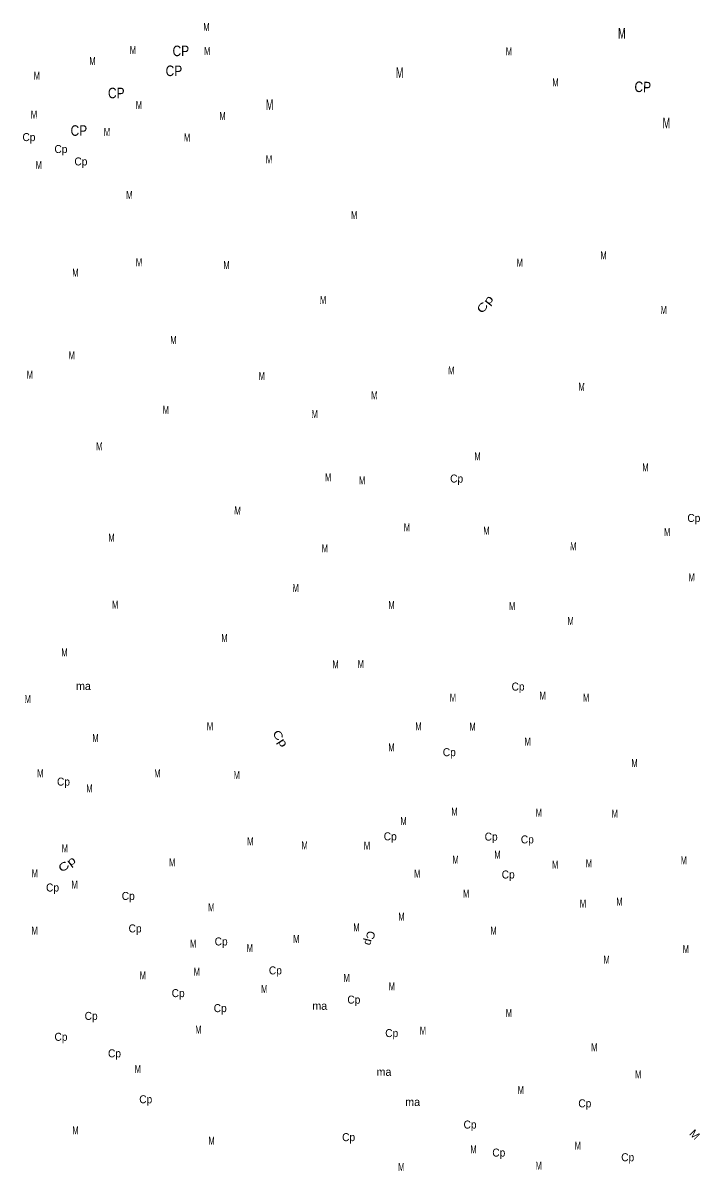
# Model space of a CAD drawing. Extents: x 713577 to 726626, y 7177731 to 7191794.
# Drawn here: x 716898 to 720111, y 7186341 to 7191792 of the extents above; entities that cross this region are included whole.
import ezdxf
from ezdxf.enums import TextEntityAlignment as Align

# ---------------------------------------------------------------- set-up
doc = ezdxf.new("R2010")
doc.units = 0
doc.header["$LTSCALE"] = 15
doc.layers.add('19', color=7, linetype='Continuous')

msp = doc.modelspace()

# ---------------------------------------------------------------- texts
at = {"layer": '19'}
for s, height, rotation, width, p in [('M', 38, 359.413, 0.65, (717768.22, 7191753.84)), ('M', 49.99, 359.812, 0.65, (719740.13, 7191717.98)), ('M', 38, 359.413, 0.65, (717419.25, 7191644.52)), ('M', 38, 359.413, 0.65, (717227.15, 7191592.51)), ('M', 38, 359.413, 0.65, (717772, 7191640.2)), ('M', 38, 359.413, 0.65, (719203.96, 7191637.88)), ('M', 49.99, 359.812, 0.65, (718685.63, 7191530.81)), ('M', 38, 359.549, 0.65, (716963.37, 7191522.42)), ('M', 38, 359.413, 0.65, (719424.92, 7191490.61)), ('CP', 50, 357.945, 0.85, (719838.79, 7191463.22)), ('M', 38, 359.549, 0.65, (717447.65, 7191383.21)), ('M', 50, 359.771, 0.65, (718068.11, 7191379.09)), ('M', 38, 359.549, 0.65, (716949.76, 7191338.04)), ('M', 38, 359.413, 0.65, (717844.69, 7191331.82)), ('M', 49.99, 359.812, 0.65, (719951.59, 7191291.84)), ('Cp', 38, 359.549, 0.95, (716925.89, 7191230.94)), ('M', 38, 359.549, 0.65, (717296.12, 7191255.64)), ('M', 38, 359.413, 0.65, (717676.41, 7191229.12)), ('Cp', 38, 359.549, 0.95, (717077.68, 7191174.32)), ('M', 38, 359.549, 0.65, (716972.43, 7191098.74)), ('Cp', 38, 359.549, 0.95, (717172.38, 7191115.43)), ('M', 38, 359.413, 0.65, (718065.11, 7191125.44)), ('M', 38, 359.549, 0.65, (717402.2, 7190955.89)), ('M', 38, 359.413, 0.65, (718469.52, 7190860.58)), ('M', 38, 359.413, 0.65, (719653.24, 7190670.15)), ('M', 38, 359.413, 0.65, (717448.08, 7190636.29)), ('M', 38, 359.413, 0.65, (717863.46, 7190623.36)), ('M', 38, 359.413, 0.65, (719255.56, 7190634.71)), ('M', 38, 359.549, 0.65, (717146.4, 7190587.65)), ('M', 38, 359.413, 0.65, (718321.81, 7190457.79)), ('Cp', 38, 52.123, 1.4, (719105.46, 7190445.02)), ('M', 38, 359.413, 0.65, (719938.74, 7190410.39)), ('M', 38, 359.413, 0.65, (717611.53, 7190268.07)), ('M', 38, 359.549, 0.65, (717129.03, 7190194.34)), ('M', 38, 359.413, 0.65, (718930.69, 7190122.96)), ('M', 38, 359.549, 0.65, (716929.98, 7190102.46)), ('M', 38, 359.413, 0.65, (718030.94, 7190097.39)), ('M', 38, 359.413, 0.65, (719549.05, 7190045.36)), ('M', 38, 359.413, 0.65, (718564.98, 7190005.35)), ('M', 38, 359.413, 0.65, (717575.74, 7189936.1)), ('M', 38, 359.413, 0.65, (718282.25, 7189916.16)), ('M', 38, 359.413, 0.65, (717259.62, 7189762.59)), ('M', 38, 359.413, 0.65, (719054.94, 7189715.97)), ('M', 38, 359.413, 0.65, (719852.06, 7189663)), ('M', 38, 359.413, 0.65, (718345.86, 7189616.34)), ('M', 38, 359.413, 0.65, (718507.28, 7189600.93)), ('Cp', 38, 359.413, 0.95, (718955.91, 7189609.88)), ('M', 38, 355.593, 0.75, (717914.45, 7189457.72)), ('Cp', 38, 359.413, 0.95, (720081.88, 7189422.65)), ('M', 38, 359.413, 0.65, (718719.78, 7189378.26)), ('M', 38, 359.413, 0.65, (719097.18, 7189362.39)), ('M', 38, 359.413, 0.65, (719955.1, 7189356.07)), ('M', 38, 359.549, 0.65, (717317.69, 7189329.29)), ('M', 38, 359.413, 0.65, (718330.33, 7189278.17)), ('M', 38, 359.413, 0.65, (719509.89, 7189287.96)), ('M', 38, 359.413, 0.65, (720071.44, 7189141.09)), ('M', 38, 359.413, 0.65, (718191.88, 7189090.85)), ('M', 38, 359.549, 0.65, (717335.16, 7189011.05)), ('M', 38, 359.99, 0.65, (718647.01, 7189009.54)), ('M', 38, 359.99, 0.65, (719219.66, 7189004.16)), ('M', 38, 359.99, 0.65, (719497.13, 7188933.39)), ('M', 38, 359.99, 0.65, (717853.98, 7188852.99)), ('M', 38, 359.549, 0.65, (717094.38, 7188784.3)), ('M', 38, 359.99, 0.65, (718381.42, 7188727.88)), ('M', 38, 359.99, 0.65, (718501.16, 7188729.84)), ('Cp', 38, 359.99, 0.95, (719247.65, 7188622.37)), ('M', 38, 359.549, 0.65, (716920, 7188563.09)), ('M', 38, 359.99, 0.65, (718938.54, 7188569.77)), ('M', 38, 359.99, 0.65, (719364.46, 7188578.8)), ('M', 38, 359.99, 0.65, (719570.63, 7188569.53)), ('M', 38, 359.99, 0.65, (717785.29, 7188433.41)), ('M', 38, 359.99, 0.65, (718774.96, 7188432.77)), ('M', 38, 359.99, 0.65, (719031.6, 7188432.07)), ('M', 38, 359.549, 0.65, (717241.71, 7188378.28)), ('Cp', 38, 303.457, 1.3, (718103.16, 7188384.49)), ('M', 38, 359.99, 0.65, (718646.63, 7188333.51)), ('M', 38, 359.99, 0.65, (719293.06, 7188361.16)), ('Cp', 38, 359.99, 0.95, (718921.34, 7188310.69)), ('M', 38, 359.99, 0.65, (716980.11, 7188211.09)), ('M', 38, 359.99, 0.65, (717535.54, 7188209.8)), ('M', 38, 359.99, 0.65, (719800.46, 7188258.68)), ('Cp', 38, 359.99, 0.95, (717089.88, 7188170.96)), ('M', 38, 359.99, 0.65, (717912.25, 7188202.15)), ('M', 38, 359.99, 0.65, (717212.98, 7188138.48)), ('M', 38, 359.99, 0.65, (718945.64, 7188028.38)), ('M', 38, 359.99, 0.65, (719346.11, 7188023.36)), ('M', 38, 359.99, 0.65, (719706.73, 7188019.2)), ('M', 38, 359.99, 0.65, (718704.23, 7187983.31)), ('M', 38, 359.99, 0.65, (717976.85, 7187886.78)), ('Cp', 38, 359.99, 0.95, (718640.88, 7187911.26)), ('Cp', 38, 359.99, 0.95, (719119.86, 7187909.85)), ('Cp', 38, 359.99, 0.95, (719291.72, 7187896.63)), ('M', 38, 359.99, 0.65, (717096.49, 7187854.15)), ('M', 38, 359.99, 0.65, (718234.47, 7187868.6)), ('M', 38, 359.99, 0.65, (718530.69, 7187866.56)), ('Cp', 38, 36.649, 1.35, (717117.47, 7187783.07)), ('M', 38, 359.99, 0.65, (717606.06, 7187787.23)), ('M', 38, 359.99, 0.65, (718951.21, 7187800.1)), ('M', 38, 359.99, 0.65, (719149.8, 7187824.15)), ('M', 38, 359.99, 0.65, (719423.91, 7187776.93)), ('M', 38, 359.99, 0.65, (719583.97, 7187782.7)), ('M', 38, 359.99, 0.65, (720033.96, 7187797.55)), ('M', 38, 359.99, 0.65, (716953.86, 7187736.25)), ('M', 38, 359.99, 0.65, (718769.1, 7187734.16)), ('Cp', 38, 359.99, 0.95, (719200.65, 7187730.06)), ('Cp', 38, 359.99, 0.95, (717038.03, 7187668.28)), ('M', 38, 359.99, 0.65, (717142.87, 7187681.46)), ('Cp', 38, 359.99, 0.95, (717397.22, 7187628.27)), ('M', 38, 359.99, 0.65, (719001.19, 7187639.7)), ('M', 38, 359.99, 0.65, (717791.41, 7187573.77)), ('M', 38, 359.99, 0.65, (719555.7, 7187592.1)), ('M', 38, 359.99, 0.65, (719728.76, 7187601.58)), ('M', 38, 359.99, 0.65, (718694.18, 7187529.98)), ('M', 38, 359.99, 0.65, (716953.15, 7187463.45)), ('Cp', 38, 359.99, 0.95, (717429.76, 7187474.05)), ('M', 38, 359.99, 0.65, (718480.49, 7187478.98)), ('M', 38, 359.99, 0.65, (719131.46, 7187463.86)), ('M', 38, 359.99, 0.65, (717705.59, 7187401.63)), ('Cp', 38, 359.99, 0.95, (717838.22, 7187412.13)), ('M', 38, 359.99, 0.65, (718195.14, 7187424.27)), ('Cp', 38, 255.964, 1.05, (718525.87, 7187451.3)), ('M', 38, 359.99, 0.65, (717974.45, 7187381.42)), ('M', 38, 359.99, 0.65, (720044.11, 7187375.98)), ('M', 38, 359.99, 0.65, (719668.01, 7187325.48)), ('M', 38, 359.99, 0.65, (717466.4, 7187251.25)), ('M', 38, 359.99, 0.65, (717722.72, 7187268.02)), ('Cp', 38, 359.99, 0.95, (718095.74, 7187274.76)), ('M', 38, 359.99, 0.65, (718433.93, 7187239.17)), ('M', 38, 359.99, 0.65, (718043.02, 7187186.16)), ('M', 38, 359.99, 0.65, (718648.6, 7187198.79)), ('Cp', 38, 359.99, 0.95, (717634.23, 7187166.9)), ('Cp', 38, 359.99, 0.95, (718468.15, 7187135.94)), ('Cp', 38, 359.99, 0.95, (717833.79, 7187095.61)), ('M', 38, 359.99, 0.65, (719204.16, 7187072.53)), ('Cp', 38, 359.99, 0.95, (717221.2, 7187058.77)), ('Cp', 38, 359.99, 0.95, (717078.02, 7186959.5)), ('M', 38, 359.99, 0.65, (717730.26, 7186993.56)), ('Cp', 38, 359.99, 0.95, (718647.91, 7186977.24)), ('M', 38, 359.99, 0.65, (718796.22, 7186988.89)), ('M', 38, 359.99, 0.65, (719609.55, 7186909.84)), ('Cp', 38, 359.99, 0.95, (717332.01, 7186880.95)), ('M', 38, 359.99, 0.65, (717442.57, 7186807.23)), ('M', 38, 359.99, 0.65, (719818.01, 7186780.83)), ('M', 38, 359.99, 0.65, (719260.64, 7186707.09)), ('Cp', 38, 359.99, 0.95, (717480.42, 7186662.87)), ('Cp', 38, 359.99, 0.95, (719564.39, 7186643.58)), ('Cp', 38, 359.99, 0.95, (719019.69, 7186542.89)), ('M', 38, 359.99, 0.65, (717146.95, 7186516.01)), ('M', 38, 359.99, 0.65, (717792.84, 7186466.08)), ('Cp', 38, 359.99, 0.95, (718443.3, 7186483.12)), ('M', 38, 359.99, 0.65, (719036.14, 7186425.67)), ('Cp', 38, 359.99, 0.95, (719156.2, 7186409.81)), ('M', 38, 359.99, 0.65, (719531.09, 7186442.82)), ('Cp', 38, 359.99, 0.95, (719768.13, 7186387.69)), ('M', 38, 359.99, 0.65, (718693.36, 7186341.15)), ('M', 38, 359.99, 0.65, (719345.63, 7186347.37))]:
    msp.add_text(s, height=height, rotation=rotation, dxfattribs=dict(at, width=width)).set_placement(p, align=Align.CENTER)
at = {"layer": '19', "width": 0.85}
for p in [(717646.96, 7191634.32), (717614.19, 7191539.72), (717340.39, 7191434.4), (717162.94, 7191256.18)]:
    msp.add_text('CP', height=50, dxfattribs=at).set_placement(p, align=Align.CENTER)
at = {"layer": '19'}
for s, rotation, p in [('ma', 359.549, (717184.45, 7188625.21)), ('ma', 359.99, (718306.38, 7187106.58)), ('ma', 359.99, (718611.08, 7186793.22)), ('ma', 359.99, (718747.27, 7186650.33)), ('M', 315, (720072.45, 7186501))]:
    msp.add_text(s, height=38, rotation=rotation, dxfattribs=at).set_placement(p, align=Align.CENTER)

doc.saveas('drawing.dxf')
